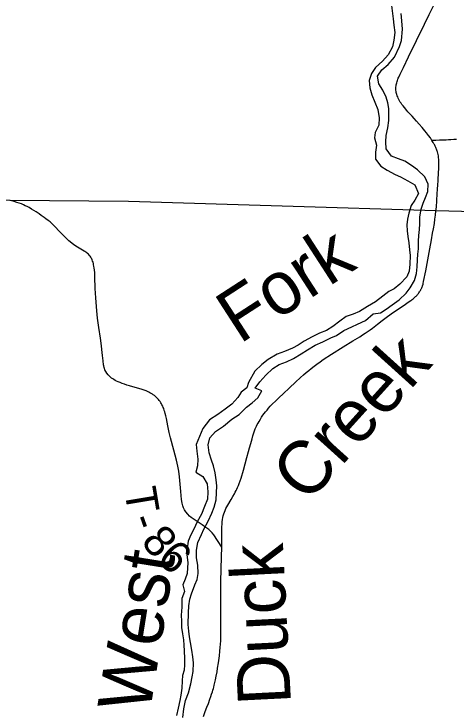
# Model space of a CAD drawing. Extents: x -10 to 158, y 8 to 33.
# Drawn here: x 126.34 to 127.131, y 26.114 to 27.363 of the extents above; entities that cross this region are included whole.
import ezdxf

# ---------------------------------------------------------------- set-up
doc = ezdxf.new("R2010")
doc.units = 0
for name, color, linetype in [('GM_X_Major_River', 7, 'Continuous'), ('GM_X_Major_River_Text', 7, 'Continuous'), ('GM_X_State_Route', 7, 'Continuous'), ('GM_X_Township_Road', 7, 'Continuous'), ('GM_X_Township_Road_Text', 7, 'Continuous'), ('GM_X_Township_Text', 7, 'Continuous')]:
    doc.layers.add(name, color=color, linetype=linetype)

msp = doc.modelspace()

# ---------------------------------------------------------------- linework, layer by layer
at = {"layer": 'GM_X_Major_River'}
for points in [[(127.0156, 27.3786), (127.0185, 27.3548), (127.0198, 27.3434), (127.0215, 27.3301), (127.0198, 27.3168), (127.0173, 27.3047), (127.0096, 27.2905), (126.9995, 27.279), (126.9871, 27.2679), (126.9797, 27.2571), (126.9757, 27.2446), (126.9766, 27.2317), (126.9802, 27.2188), (126.9912, 27.1924), (126.9937, 27.1777), (126.9927, 27.1648), (126.9864, 27.1518), (126.985, 27.1423), (126.9886, 27.129), (126.9869, 27.1165), (126.9867, 27.104), (126.9963, 27.0912), (127.0078, 27.0842), (127.0219, 27.0764), (127.0315, 27.0724), (127.0448, 27.0653), (127.0571, 27.0579), (127.0637, 27.0428), (127.0571, 27.0306), (127.0508, 27.021), (127.0464, 27.0073), (127.0443, 26.9967), (127.0433, 26.9868), (127.0434, 26.9758), (127.0447, 26.9656), (127.0467, 26.9542), (127.048, 26.9417), (127.0489, 26.9315), (127.0484, 26.9163), (127.0474, 26.9038), (127.043, 26.8935), (127.0307, 26.8804), (127.0205, 26.8723), (127.0108, 26.8672), (127.0002, 26.8591), (126.9871, 26.8487), (126.9724, 26.8406), (126.9585, 26.8316), (126.9472, 26.8269), (126.9348, 26.823), (126.9231, 26.8141), (126.9108, 26.8048), (126.8995, 26.7978), (126.8866, 26.7931), (126.8735, 26.7865), (126.8595, 26.7787), (126.849, 26.7717), (126.8385, 26.7659), (126.8242, 26.7604), (126.8113, 26.7557), (126.7952, 26.746), (126.7835, 26.7371), (126.7712, 26.7252), (126.7601, 26.7045), (126.7568, 26.695)], [(126.7716, 26.6944), (126.7802, 26.7059), (126.791, 26.7178), (126.8033, 26.7298), (126.815, 26.7371), (126.8278, 26.7419), (126.8402, 26.7477), (126.8538, 26.7559), (126.8654, 26.7632), (126.879, 26.7714), (126.8929, 26.7776), (126.9069, 26.7847), (126.9174, 26.789), (126.9302, 26.7975), (126.9445, 26.8045), (126.9551, 26.8088), (126.9694, 26.8155), (126.9829, 26.8274), (126.9957, 26.8295), (127.0063, 26.8357), (127.0168, 26.8434), (127.0295, 26.8523), (127.0419, 26.8643), (127.049, 26.8738), (127.0567, 26.8868), (127.0604, 26.8994), (127.0613, 26.9112), (127.0619, 26.9241), (127.0626, 26.9339), (127.0636, 26.9438), (127.0641, 26.9575), (127.0647, 26.9674), (127.0657, 26.9784), (127.0664, 26.9886), (127.0662, 27.0011), (127.0687, 27.0148), (127.0723, 27.0251), (127.0763, 27.0354), (127.0807, 27.0461), (127.0809, 27.0594), (127.0751, 27.0722), (127.0624, 27.0849), (127.0513, 27.0927), (127.0394, 27.1002), (127.028, 27.1045), (127.0158, 27.1093), (127.0058, 27.1225), (127.0056, 27.135), (127.0062, 27.146), (127.0091, 27.16), (127.0108, 27.173), (127.011, 27.1828), (127.0109, 27.1942), (127.0092, 27.2044), (127.006, 27.2146), (127.0002, 27.2274), (126.9932, 27.2383), (126.9907, 27.252), (126.9986, 27.2635), (127.0098, 27.2731), (127.021, 27.2865), (127.0302, 27.3052), (127.0335, 27.3159), (127.0355, 27.3364), (127.0341, 27.3512), (127.0328, 27.3641)], [(126.7568, 26.695), (126.747, 26.6877), (126.7407, 26.6777), (126.7303, 26.6658), (126.7179, 26.6569), (126.7051, 26.6473), (126.6901, 26.6383), (126.6785, 26.6226), (126.6664, 26.594), (126.6673, 26.5819), (126.669, 26.5679), (126.6684, 26.5561), (126.666, 26.5443), (126.6782, 26.5369), (126.6859, 26.5237), (126.6869, 26.5093), (126.6863, 26.496), (126.6812, 26.4831), (126.6757, 26.4697), (126.6679, 26.4559), (126.662, 26.4426), (126.6568, 26.4327), (126.6521, 26.4212), (126.65, 26.4079), (126.6494, 26.3969), (126.6515, 26.3833), (126.6502, 26.3635), (126.6465, 26.3532), (126.6425, 26.3433), (126.6453, 26.3312), (126.6406, 26.3186), (126.6408, 26.3035), (126.6395, 26.289), (126.64, 26.2784), (126.6401, 26.2666), (126.6418, 26.2553), (126.6435, 26.2447), (126.6444, 26.2352), (126.6449, 26.225), (126.6454, 26.2117), (126.6452, 26.2003), (126.6446, 26.1908), (126.642, 26.1813), (126.6414, 26.1718), (126.6408, 26.1585), (126.6387, 26.146), (126.637, 26.1365), (126.6341, 26.1228), (126.6309, 26.1098)], [(126.6423, 26.1058), (126.6444, 26.1214), (126.6472, 26.1362), (126.6523, 26.15), (126.657, 26.1663), (126.6591, 26.1785), (126.6609, 26.1884), (126.6615, 26.204), (126.6606, 26.2146), (126.6585, 26.2263), (126.656, 26.2403), (126.6544, 26.2501), (126.6531, 26.2604), (126.6522, 26.2725), (126.6527, 26.293), (126.6529, 26.3055), (126.655, 26.3177), (126.6579, 26.3272), (126.6637, 26.3432), (126.6682, 26.3528), (126.6699, 26.3634), (126.669, 26.3782), (126.6669, 26.3911), (126.6667, 26.4051), (126.6695, 26.4188), (126.6758, 26.4329), (126.6802, 26.4428), (126.688, 26.457), (126.6942, 26.4711), (126.6983, 26.4818), (126.7019, 26.4951), (126.7028, 26.5073), (126.7034, 26.5198), (126.7021, 26.5311), (126.7001, 26.5433), (126.6973, 26.5557), (126.6937, 26.5659), (126.6897, 26.5788), (126.6877, 26.5932), (126.6905, 26.6057), (126.701, 26.6169), (126.7149, 26.6269), (126.7303, 26.6393), (126.743, 26.6478), (126.7565, 26.6605), (126.7663, 26.6686), (126.7764, 26.6774), (126.7838, 26.6901), (126.7716, 26.6944)]]:
    msp.add_lwpolyline(points, dxfattribs=at)
at = {"layer": 'GM_X_State_Route'}
for points in [[(127.0951, 27.0115), (127.0958, 27.0184), (127.0966, 27.0298), (127.0975, 27.0417), (127.0981, 27.0503), (127.0986, 27.0578), (127.099, 27.0651), (127.0993, 27.0708), (127.0995, 27.0758), (127.0997, 27.0802), (127.1, 27.0865), (127.1002, 27.0927), (127.1002, 27.0965), (127.1001, 27.0996), (127.1, 27.104), (127.0998, 27.1066), (127.0995, 27.1096), (127.0991, 27.1122), (127.0984, 27.1149), (127.0979, 27.117), (127.0974, 27.1185), (127.0968, 27.1202), (127.0962, 27.1218), (127.0957, 27.1231), (127.0951, 27.1246), (127.0945, 27.1259), (127.0938, 27.1274), (127.0931, 27.1288), (127.0925, 27.1299), (127.0915, 27.1316), (127.0903, 27.1336), (127.088, 27.1373), (127.0851, 27.1418), (127.0819, 27.1461), (127.0784, 27.1507), (127.0754, 27.1544), (127.0702, 27.1606), (127.0653, 27.1663), (127.0604, 27.1719), (127.0564, 27.1764), (127.0523, 27.1807), (127.0482, 27.1851), (127.0451, 27.1887), (127.0429, 27.1912), (127.0387, 27.1962), (127.0362, 27.1991), (127.0342, 27.2018), (127.0327, 27.2038), (127.0313, 27.2061), (127.03, 27.2083), (127.0288, 27.2106), (127.0277, 27.2129), (127.0268, 27.2151), (127.0259, 27.217), (127.0251, 27.2193), (127.0245, 27.2214), (127.024, 27.2232), (127.0238, 27.225), (127.0235, 27.2272), (127.0234, 27.229), (127.0234, 27.2309), (127.0236, 27.2328), (127.0239, 27.2351), (127.0242, 27.2368), (127.0246, 27.2385), (127.0251, 27.2405), (127.0257, 27.2427), (127.0265, 27.2448), (127.0271, 27.2468), (127.0278, 27.2485), (127.0285, 27.2502), (127.0313, 27.2561), (127.0368, 27.2679), (127.0462, 27.2868), (127.0603, 27.3159), (127.0746, 27.3455), (127.0828, 27.3622), (127.093, 27.3828)], [(126.6793, 26.1079), (126.6826, 26.1165), (126.6855, 26.1242), (126.6881, 26.1311), (126.691, 26.1388), (126.6926, 26.1438), (126.694, 26.1479), (126.6953, 26.1518), (126.6962, 26.155), (126.697, 26.1577), (126.6978, 26.1605), (126.6986, 26.1636), (126.6997, 26.1683), (126.7008, 26.1733), (126.7022, 26.1801), (126.7036, 26.1878), (126.7047, 26.1941), (126.7061, 26.2039), (126.7079, 26.2163), (126.7088, 26.2245), (126.7094, 26.231), (126.7099, 26.2371), (126.7103, 26.2432), (126.7105, 26.2499), (126.7105, 26.2562), (126.7105, 26.2617), (126.7104, 26.2722), (126.7105, 26.2879), (126.7106, 26.2983), (126.7106, 26.3256), (126.7107, 26.3493), (126.7116, 26.3934), (126.712, 26.4106), (126.7121, 26.423), (126.7122, 26.4416), (126.7123, 26.4468), (126.7125, 26.4514), (126.7128, 26.4558), (126.7135, 26.46), (126.714, 26.4633), (126.7148, 26.4666), (126.7157, 26.4698), (126.7168, 26.473), (126.7179, 26.4761), (126.7193, 26.4793), (126.7211, 26.4824), (126.7229, 26.4858), (126.7289, 26.4959), (126.732, 26.5011), (126.7346, 26.5056), (126.7362, 26.5085), (126.7378, 26.5116), (126.7391, 26.5144), (126.7405, 26.5173), (126.7418, 26.5207), (126.7433, 26.5243), (126.7465, 26.5337), (126.7507, 26.5481), (126.757, 26.5708), (126.7599, 26.5815), (126.7618, 26.5881), (126.7639, 26.5958), (126.7664, 26.6043), (126.7679, 26.6096), (126.7695, 26.6147), (126.7709, 26.6186), (126.7721, 26.622), (126.7731, 26.6245), (126.7742, 26.627), (126.7755, 26.6295), (126.7769, 26.6321), (126.7788, 26.6353), (126.7811, 26.6395), (126.7834, 26.6431), (126.7856, 26.6464), (126.788, 26.6496), (126.7901, 26.6523), (126.793, 26.6556), (126.7957, 26.6588), (126.7988, 26.6623), (126.8029, 26.6667), (126.8079, 26.6715), (126.8147, 26.6781), (126.8219, 26.6848), (126.8332, 26.6954), (126.8439, 26.7055), (126.8528, 26.7136), (126.8581, 26.7184), (126.863, 26.7226), (126.8675, 26.7263), (126.8721, 26.73), (126.8772, 26.734), (126.882, 26.7375), (126.8878, 26.7418), (126.8936, 26.7457), (126.9082, 26.7552), (126.9292, 26.7684), (126.9466, 26.779), (126.9588, 26.7864), (126.964, 26.7898), (126.9687, 26.7928), (126.9739, 26.7964), (126.9777, 26.7991), (126.9814, 26.8018), (126.9904, 26.8089), (126.999, 26.8158), (127.0084, 26.8228), (127.0189, 26.8304), (127.0291, 26.8372), (127.0407, 26.8448), (127.0455, 26.8481), (127.0501, 26.8512), (127.0513, 26.8521), (127.0527, 26.8531), (127.0542, 26.8542), (127.0558, 26.8556), (127.0574, 26.8572), (127.0586, 26.8582), (127.0595, 26.8593), (127.0613, 26.861), (127.0621, 26.862), (127.063, 26.863), (127.0637, 26.864), (127.0645, 26.8651), (127.0659, 26.8671), (127.0665, 26.8681), (127.0672, 26.869), (127.0678, 26.8701), (127.0683, 26.871), (127.0688, 26.872), (127.0693, 26.873), (127.0698, 26.8742), (127.0704, 26.8755), (127.0709, 26.8768), (127.0713, 26.878), (127.0716, 26.879), (127.072, 26.8803), (127.0723, 26.8819), (127.0731, 26.8854), (127.0768, 26.9041), (127.0842, 26.9439), (127.087, 26.9596), (127.0892, 26.9717), (127.0907, 26.9796), (127.0923, 26.9892), (127.0933, 26.9968), (127.0943, 27.0038), (127.0951, 27.0115)]]:
    msp.add_lwpolyline(points, dxfattribs=at)
at = {"layer": 'GM_X_Township_Road'}
for points in [[(127.1316, 27.1393), (127.1269, 27.139), (127.122, 27.1386), (127.1178, 27.1383), (127.1134, 27.138), (127.1072, 27.1377), (127.1016, 27.1376), (127.095, 27.1374), (127.088, 27.1373)], [(126.6769, 26.4503), (126.6734, 26.4526), (126.6662, 26.4574), (126.6625, 26.4597), (126.6575, 26.4632), (126.6542, 26.4661), (126.6512, 26.4692), (126.6478, 26.4737), (126.6455, 26.4773), (126.6438, 26.4807), (126.6426, 26.4842), (126.6414, 26.489), (126.6402, 26.4957), (126.6387, 26.5099), (126.6365, 26.5359), (126.6352, 26.5464), (126.6338, 26.555), (126.6313, 26.5659), (126.6265, 26.5839), (126.6205, 26.6061), (126.6183, 26.6152), (126.6158, 26.6273), (126.613, 26.6407), (126.612, 26.6454), (126.611, 26.6491), (126.6101, 26.6523), (126.6092, 26.655), (126.6082, 26.658), (126.6073, 26.6602), (126.6064, 26.6624), (126.6052, 26.6647), (126.6043, 26.6665), (126.6031, 26.6685), (126.6017, 26.6706), (126.6002, 26.6726), (126.5988, 26.6743), (126.597, 26.6763), (126.5954, 26.6779), (126.5934, 26.6797), (126.5916, 26.6813), (126.5895, 26.6828), (126.588, 26.684), (126.5859, 26.6853), (126.5837, 26.6865), (126.5816, 26.6876), (126.5793, 26.6887), (126.577, 26.6897), (126.5734, 26.691), (126.57, 26.6921), (126.5473, 26.6987), (126.5422, 26.7002), (126.5379, 26.7017), (126.5341, 26.7031), (126.5303, 26.7045), (126.5268, 26.706), (126.5241, 26.7073), (126.5215, 26.7086), (126.5192, 26.71), (126.517, 26.7115), (126.515, 26.7128), (126.5132, 26.7143), (126.5117, 26.7156), (126.5091, 26.7182), (126.5068, 26.7212), (126.5049, 26.7245), (126.5032, 26.7277), (126.5023, 26.7299), (126.5018, 26.7318), (126.5012, 26.7344), (126.5006, 26.7366), (126.4999, 26.7434), (126.499, 26.7533), (126.4964, 26.7749), (126.495, 26.7841), (126.4921, 26.8031), (126.49, 26.8197), (126.4887, 26.8327), (126.4867, 26.8562), (126.4858, 26.873), (126.4851, 26.8935), (126.4848, 26.9007), (126.4844, 26.9059), (126.484, 26.9092), (126.4835, 26.9127), (126.483, 26.9152), (126.4825, 26.9175), (126.4819, 26.9197), (126.4812, 26.9217), (126.4804, 26.9239), (126.4795, 26.9257), (126.4788, 26.9272), (126.478, 26.9285), (126.4768, 26.9304), (126.4755, 26.932), (126.4737, 26.934), (126.472, 26.9354), (126.4705, 26.9366), (126.469, 26.9377), (126.4675, 26.9387), (126.4659, 26.9396), (126.4572, 26.9446), (126.4543, 26.9464), (126.4509, 26.9486), (126.4472, 26.9512), (126.4444, 26.9534), (126.4412, 26.9561), (126.4387, 26.9582), (126.4355, 26.9611), (126.4319, 26.9646), (126.4278, 26.9688), (126.422, 26.9748), (126.4134, 26.9837), (126.4105, 26.9866), (126.408, 26.9889), (126.405, 26.9917), (126.4019, 26.9941), (126.3977, 26.9974), (126.3945, 26.9999), (126.3893, 27.0035), (126.3854, 27.0063), (126.3799, 27.01), (126.376, 27.0124), (126.3719, 27.0148), (126.3674, 27.0174), (126.3641, 27.0192), (126.3608, 27.0208), (126.3573, 27.0224), (126.354, 27.0238), (126.3499, 27.0253), (126.3458, 27.0267), (126.3408, 27.0282), (126.3351, 27.0299)], [(126.712, 26.4106), (126.6976, 26.4326), (126.695, 26.436), (126.6921, 26.4392), (126.6888, 26.4421), (126.6838, 26.4457), (126.6769, 26.4503)]]:
    msp.add_lwpolyline(points, dxfattribs=at)
at = {"layer": 'GM_X_Township_Text'}
msp.add_lwpolyline([(126.1038, 30.3865), (126.1038, 27.0364), (126.3333, 27.0308), (126.5452, 27.0287), (127.0949, 27.0121), (127.9467, 26.9899), (128.0604, 26.987), (128.3868, 26.9847), (128.4032, 28.3535), (128.4042, 28.3758)], dxfattribs=at)

# ---------------------------------------------------------------- texts
at = {"layer": 'GM_X_Major_River_Text'}
for s, height, rotation, p in [('Fork', 0.0947, 32.9054, (126.744, 26.7726)), ('Creek', 0.09471, 47.9058, (126.8645, 26.4864)), ('Duck', 0.09472, 92.8975, (126.836, 26.1305)), ('West', 0.09472, 80.9004, (126.5831, 26.1115))]:
    msp.add_text(s, height=height, rotation=rotation, dxfattribs=at).set_placement(p)
at = {"layer": 'GM_X_Township_Road_Text'}
for s, rotation, p in [('T', 279.4799, (126.5375, 26.513)), ('-', 289.652, (126.5473, 26.4604)), ('8', 310.0312, (126.566, 26.4194)), ('6', 317.4219, (126.594, 26.3869))]:
    msp.add_text(s, height=0.0568, rotation=rotation, dxfattribs=at).set_placement(p)

doc.saveas('drawing.dxf')
